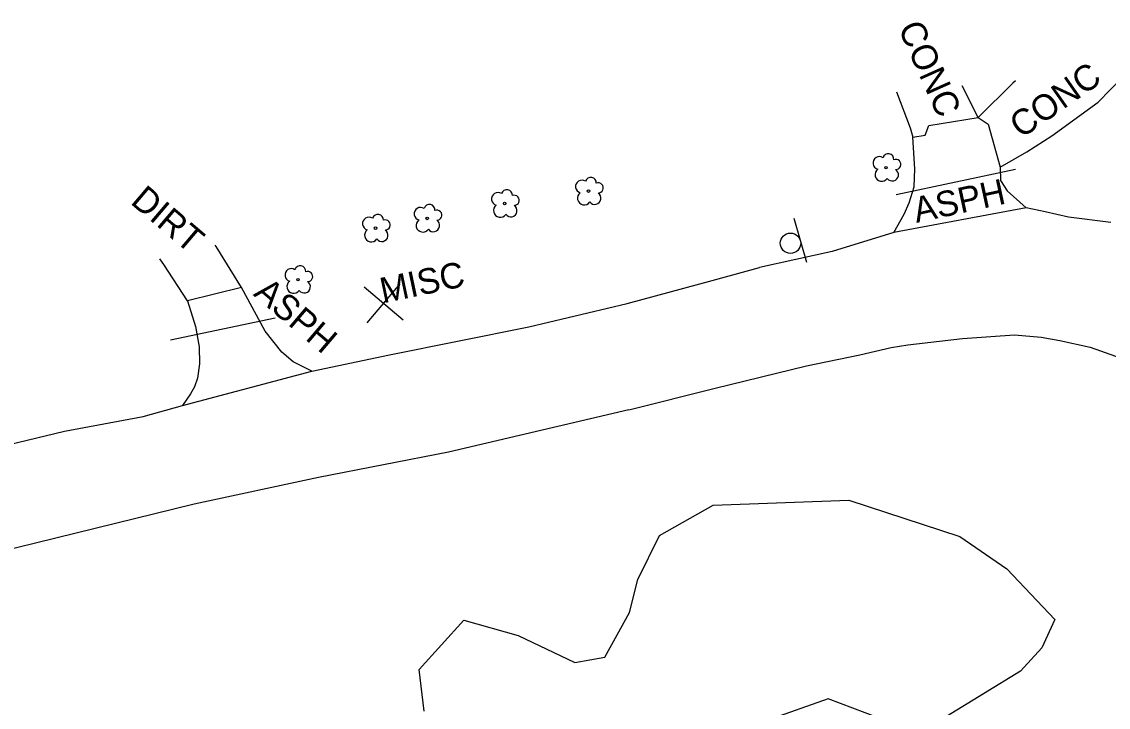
# Model space of a CAD drawing. Extents: x 2076109 to 2080761, y 592812 to 596750.
# Drawn here: x 2077526.3 to 2077739.5, y 596055.5 to 596190.1 of the extents above; entities that cross this region are included whole.
import ezdxf

# ---------------------------------------------------------------- set-up
doc = ezdxf.new("R2010")
doc.units = 0
for name, color, linetype in [('RD_EX_BldgApp', 7, 'Continuous'), ('RD_EX_Conc', 7, 'Continuous'), ('RD_EX_Conc_txCode', 7, 'Continuous'), ('RD_EX_DR_Pipe', 7, 'Continuous'), ('RD_EX_Driveway', 7, 'Continuous'), ('RD_EX_Driveway_txCode', 7, 'Continuous'), ('RD_EX_Misc', 7, 'Continuous'), ('RD_EX_Misc_txCode', 7, 'Continuous'), ('RD_EX_Road', 7, 'Continuous'), ('RD_EX_VEG', 7, 'Continuous')]:
    doc.layers.add(name, color=color, linetype=linetype)

msp = doc.modelspace()

# ---------------------------------------------------------------- linework, layer by layer
at = {"layer": 'RD_EX_BldgApp'}
msp.add_line((2077680.36, 596142.86), (2077677.89, 596151.51), dxfattribs=at)
msp.add_line((2077680.36, 596142.86), (2077677.89, 596151.51), dxfattribs=at)
msp.add_circle((2077677.17, 596146.65), 2, dxfattribs=at)
msp.add_circle((2077677.17, 596146.65), 2, dxfattribs=at)
at = {"layer": 'RD_EX_Conc'}
for points in [[(2077718.29, 596161.57), (2077723.52, 596164.57), (2077728.43, 596167.76), (2077737.52, 596174.32), (2077742.37, 596179.33)], [(2077718.29, 596161.57), (2077723.52, 596164.57), (2077728.43, 596167.76), (2077737.52, 596174.32), (2077742.37, 596179.33)], [(2077713.99, 596171.32), (2077710.83, 596177.58)], [(2077713.99, 596171.32), (2077710.83, 596177.58)], [(2077721.33, 596178.55), (2077720.78, 596178.06), (2077713.99, 596171.32)], [(2077721.33, 596178.55), (2077720.78, 596178.06), (2077713.99, 596171.32)], [(2077697.97, 596176.38), (2077700.63, 596169.28), (2077701.17, 596167.47)], [(2077697.97, 596176.38), (2077700.63, 596169.28), (2077701.17, 596167.47)], [(2077701.17, 596167.47), (2077703.6, 596167.89), (2077704.29, 596169.74), (2077713.99, 596171.32), (2077715.94, 596170.04), (2077718.29, 596161.57)], [(2077701.17, 596167.47), (2077703.6, 596167.89), (2077704.29, 596169.74), (2077713.99, 596171.32), (2077715.94, 596170.04), (2077718.29, 596161.57)]]:
    msp.add_lwpolyline(points, dxfattribs=at)
at = {"layer": 'RD_EX_DR_Pipe'}
for p, q in [((2077697.88, 596156.25), (2077721.33, 596161.22)), ((2077697.88, 596156.25), (2077721.33, 596161.22)), ((2077555.48, 596127.68), (2077576.04, 596132.01)), ((2077555.48, 596127.68), (2077576.04, 596132.01))]:
    msp.add_line(p, q, dxfattribs=at)
at = {"layer": 'RD_EX_Driveway'}
for points in [[(2077697.42, 596148.75), (2077699.44, 596152.39), (2077700.45, 596154.61), (2077701.41, 596157.7), (2077701.57, 596161.25), (2077701.17, 596167.47)], [(2077697.42, 596148.75), (2077699.44, 596152.39), (2077700.45, 596154.61), (2077701.41, 596157.7), (2077701.57, 596161.25), (2077701.17, 596167.47)], [(2077718.29, 596161.57), (2077718.38, 596158.97), (2077719.67, 596156.96), (2077723.43, 596153.58)], [(2077718.29, 596161.57), (2077718.38, 596158.97), (2077719.67, 596156.96), (2077723.43, 596153.58)], [(2077569.41, 596137.98), (2077564.46, 596146.04), (2077564.29, 596146.29)], [(2077569.41, 596137.98), (2077564.46, 596146.04), (2077564.29, 596146.29)], [(2077558.83, 596135.36), (2077554.18, 596142.51), (2077553.43, 596143.6)], [(2077558.83, 596135.36), (2077554.18, 596142.51), (2077553.43, 596143.6)], [(2077583.22, 596121.55), (2077579.54, 596123.38), (2077577.37, 596125.27), (2077574.1, 596129.39), (2077569.41, 596137.98), (2077558.83, 596135.36), (2077560.39, 596130.3), (2077561.14, 596126.3), (2077561.18, 596122.99), (2077560.78, 596120.19), (2077560.18, 596118.44), (2077559.39, 596117.08), (2077557.84, 596114.81)], [(2077583.22, 596121.55), (2077579.54, 596123.38), (2077577.37, 596125.27), (2077574.1, 596129.39), (2077569.41, 596137.98), (2077558.83, 596135.36), (2077560.39, 596130.3), (2077561.14, 596126.3), (2077561.18, 596122.99), (2077560.78, 596120.19), (2077560.18, 596118.44), (2077559.39, 596117.08), (2077557.84, 596114.81)]]:
    msp.add_lwpolyline(points, dxfattribs=at)
at = {"layer": 'RD_EX_Misc'}
for p, q in [((2077593.51, 596138.08), (2077601.13, 596131.6)), ((2077593.51, 596138.08), (2077601.13, 596131.6)), ((2077594.08, 596131.03), (2077600.56, 596138.65)), ((2077594.08, 596131.03), (2077600.56, 596138.65))]:
    msp.add_line(p, q, dxfattribs=at)
at = {"layer": 'RD_EX_Road'}
for points in [[(2077740.04, 596150.73), (2077731.71, 596151.8), (2077727.13, 596152.79), (2077723.43, 596153.58), (2077697.42, 596148.75), (2077685.33, 596145), (2077671.06, 596141.87)], [(2077740.04, 596150.73), (2077731.71, 596151.8), (2077727.13, 596152.79), (2077723.43, 596153.58), (2077697.42, 596148.75), (2077685.33, 596145), (2077671.06, 596141.87)], [(2077514.57, 596104.92), (2077534.69, 596109.77), (2077550.16, 596112.66), (2077557.84, 596114.81), (2077583.22, 596121.55), (2077598.46, 596124.77), (2077625.81, 596130.25), (2077645.08, 596134.8), (2077661.81, 596139.35), (2077671.06, 596141.87)], [(2077514.57, 596104.92), (2077534.69, 596109.77), (2077550.16, 596112.66), (2077557.84, 596114.81), (2077583.22, 596121.55), (2077598.46, 596124.77), (2077625.81, 596130.25), (2077645.08, 596134.8), (2077661.81, 596139.35), (2077671.06, 596141.87)], [(2077645.43, 596113.93), (2077662.35, 596118.22), (2077680.33, 596122.58), (2077690.78, 596124.72), (2077696.91, 596126.16), (2077700.22, 596126.7), (2077710.95, 596127.97), (2077721.12, 596128.64), (2077726.34, 596128.18), (2077730, 596127.57), (2077735.96, 596126.24), (2077743.91, 596123.42)], [(2077645.43, 596113.93), (2077662.35, 596118.22), (2077680.33, 596122.58), (2077690.78, 596124.72), (2077696.91, 596126.16), (2077700.22, 596126.7), (2077710.95, 596127.97), (2077721.12, 596128.64), (2077726.34, 596128.18), (2077730, 596127.57), (2077735.96, 596126.24), (2077743.91, 596123.42)], [(2077645.43, 596113.93), (2077610.05, 596105.64), (2077584.56, 596100.66), (2077560.11, 596095.44), (2077525.26, 596086.84), (2077497.93, 596080.19), (2077464.38, 596072.84), (2077441.23, 596067.85), (2077413.99, 596061.96), (2077390.93, 596057.62), (2077368.72, 596053.41), (2077344.12, 596049.05), (2077310.8, 596045.6), (2077284.61, 596043.93)], [(2077645.43, 596113.93), (2077610.05, 596105.64), (2077584.56, 596100.66), (2077560.11, 596095.44), (2077525.26, 596086.84), (2077497.93, 596080.19), (2077464.38, 596072.84), (2077441.23, 596067.85), (2077413.99, 596061.96), (2077390.93, 596057.62), (2077368.72, 596053.41), (2077344.12, 596049.05), (2077310.8, 596045.6), (2077284.61, 596043.93)]]:
    msp.add_lwpolyline(points, dxfattribs=at)
at = {"layer": 'RD_EX_VEG'}
for points in [[(2077605.27, 596054.78), (2077604.29, 596062.96), (2077613.04, 596072.65), (2077623.74, 596069.66), (2077634.84, 596064.31), (2077640.72, 596065.4), (2077645.58, 596074.18), (2077647.2, 596080.66), (2077651.43, 596089.28), (2077661.99, 596095.24), (2077688.62, 596096.2), (2077710.39, 596089.09), (2077719.64, 596082.73), (2077729.04, 596072.76), (2077726.52, 596067.18), (2077722.31, 596062.63), (2077707.81, 596053.75)], [(2077605.27, 596054.78), (2077604.29, 596062.96), (2077613.04, 596072.65), (2077623.74, 596069.66), (2077634.84, 596064.31), (2077640.72, 596065.4), (2077645.58, 596074.18), (2077647.2, 596080.66), (2077651.43, 596089.28), (2077661.99, 596095.24), (2077688.62, 596096.2), (2077710.39, 596089.09), (2077719.64, 596082.73), (2077729.04, 596072.76), (2077726.52, 596067.18), (2077722.31, 596062.63), (2077707.81, 596053.75)], [(2077699.09, 596051.73), (2077684.56, 596057.21), (2077672.71, 596053)], [(2077699.09, 596051.73), (2077684.56, 596057.21), (2077672.71, 596053)]]:
    msp.add_lwpolyline(points, dxfattribs=at)
for centre in [(2077695.91, 596161.5), (2077695.91, 596161.5), (2077637.53, 596156.89), (2077637.53, 596156.89), (2077621.06, 596154.45), (2077621.06, 596154.45), (2077605.86, 596151.53), (2077605.86, 596151.53), (2077595.74, 596149.62), (2077595.74, 596149.62), (2077580.51, 596139.51), (2077580.51, 596139.51)]:
    msp.add_circle(centre, 0.25, dxfattribs=at)
for centre, radius, start, end in [((2077694.62, 596162.4), 1.26, 56.211, 254.4932), ((2077694.62, 596162.4), 1.26, 56.211, 254.4932), ((2077696.36, 596163.15), 1.08, 354.7355, 164.5153), ((2077696.36, 596163.15), 1.08, 354.7355, 164.5153), ((2077697.81, 596162.13), 0.995, 268.5218, 111.806), ((2077697.81, 596162.13), 0.995, 268.5218, 111.806), ((2077695.07, 596160.13), 1.32, 126.6419, 325.5182), ((2077695.07, 596160.13), 1.32, 126.6419, 325.5182), ((2077697.13, 596160.1), 1.22, 216.3259, 57.8639), ((2077697.13, 596160.1), 1.22, 216.3259, 57.8639), ((2077636.23, 596157.78), 1.26, 56.0792, 254.3614), ((2077636.23, 596157.78), 1.26, 56.0792, 254.3614), ((2077637.98, 596158.53), 1.08, 354.6037, 164.3834), ((2077637.98, 596158.53), 1.08, 354.6037, 164.3834), ((2077639.43, 596157.51), 0.995, 268.39, 111.6741), ((2077639.43, 596157.51), 0.995, 268.39, 111.6741), ((2077619.76, 596155.34), 1.26, 56.0792, 254.3614), ((2077619.76, 596155.34), 1.26, 56.0792, 254.3614), ((2077621.51, 596156.1), 1.08, 354.6037, 164.3834), ((2077621.51, 596156.1), 1.08, 354.6037, 164.3834), ((2077622.95, 596155.07), 0.995, 268.39, 111.6741), ((2077622.95, 596155.07), 0.995, 268.39, 111.6741), ((2077636.68, 596155.51), 1.32, 126.51, 325.3863), ((2077636.68, 596155.51), 1.32, 126.51, 325.3863), ((2077638.75, 596155.48), 1.22, 216.1941, 57.732), ((2077638.75, 596155.48), 1.22, 216.1941, 57.732), ((2077604.56, 596152.43), 1.26, 56.0792, 254.3614), ((2077604.56, 596152.43), 1.26, 56.0792, 254.3614), ((2077606.31, 596153.18), 1.08, 354.6037, 164.3834), ((2077606.31, 596153.18), 1.08, 354.6037, 164.3834), ((2077620.21, 596153.07), 1.32, 126.51, 325.3863), ((2077620.21, 596153.07), 1.32, 126.51, 325.3863), ((2077622.28, 596153.05), 1.22, 216.1941, 57.732), ((2077622.28, 596153.05), 1.22, 216.1941, 57.732), ((2077594.45, 596150.51), 1.26, 56.0792, 254.3614), ((2077594.45, 596150.51), 1.26, 56.0792, 254.3614), ((2077596.2, 596151.26), 1.08, 354.6037, 164.3834), ((2077596.2, 596151.26), 1.08, 354.6037, 164.3834), ((2077607.76, 596152.15), 0.995, 268.39, 111.6741), ((2077607.76, 596152.15), 0.995, 268.39, 111.6741), ((2077597.64, 596150.24), 0.995, 268.39, 111.6741), ((2077597.64, 596150.24), 0.995, 268.39, 111.6741), ((2077605.01, 596150.16), 1.32, 126.51, 325.3863), ((2077605.01, 596150.16), 1.32, 126.51, 325.3863), ((2077607.08, 596150.13), 1.22, 216.1941, 57.732), ((2077607.08, 596150.13), 1.22, 216.1941, 57.732), ((2077594.9, 596148.24), 1.32, 126.51, 325.3863), ((2077594.9, 596148.24), 1.32, 126.51, 325.3863), ((2077596.96, 596148.21), 1.22, 216.1941, 57.732), ((2077596.96, 596148.21), 1.22, 216.1941, 57.732), ((2077579.22, 596140.4), 1.26, 56.0792, 254.3614), ((2077579.22, 596140.4), 1.26, 56.0792, 254.3614), ((2077580.96, 596141.15), 1.08, 354.6037, 164.3834), ((2077580.96, 596141.15), 1.08, 354.6037, 164.3834), ((2077582.41, 596140.13), 0.995, 268.39, 111.6741), ((2077582.41, 596140.13), 0.995, 268.39, 111.6741), ((2077579.66, 596138.13), 1.32, 126.51, 325.3863), ((2077579.66, 596138.13), 1.32, 126.51, 325.3863), ((2077581.73, 596138.1), 1.22, 216.1941, 57.732), ((2077581.73, 596138.1), 1.22, 216.1941, 57.732)]:
    msp.add_arc(centre, radius, start, end, dxfattribs=at)

# ---------------------------------------------------------------- texts
at = {"layer": 'RD_EX_Conc_txCode'}
for rotation, p in [(294.1056, (2077698.21, 596188.94)), (294.1056, (2077698.21, 596188.94)), (35.0236, (2077722.44, 596167.1)), (35.0236, (2077722.44, 596167.1))]:
    msp.add_text('CONC', height=5, rotation=rotation, dxfattribs=at).set_placement(p)
at = {"layer": 'RD_EX_Driveway_txCode'}
for s, rotation, p in [('DIRT', 319.6274, (2077547.44, 596154.55)), ('DIRT', 319.6274, (2077547.44, 596154.55)), ('ASPH', 12.1928, (2077701.87, 596150.63)), ('ASPH', 12.1928, (2077701.87, 596150.63)), ('ASPH', 319.6274, (2077571.58, 596136.51)), ('ASPH', 319.6274, (2077571.58, 596136.51))]:
    msp.add_text(s, height=5, rotation=rotation, dxfattribs=at).set_placement(p)
at = {"layer": 'RD_EX_Misc_txCode'}
msp.add_text(' MISC', height=5, rotation=11.8491, dxfattribs=at).set_placement((2077595.37, 596134.46))
msp.add_text(' MISC', height=5, rotation=11.8491, dxfattribs=at).set_placement((2077595.37, 596134.46))

doc.saveas('drawing.dxf')
